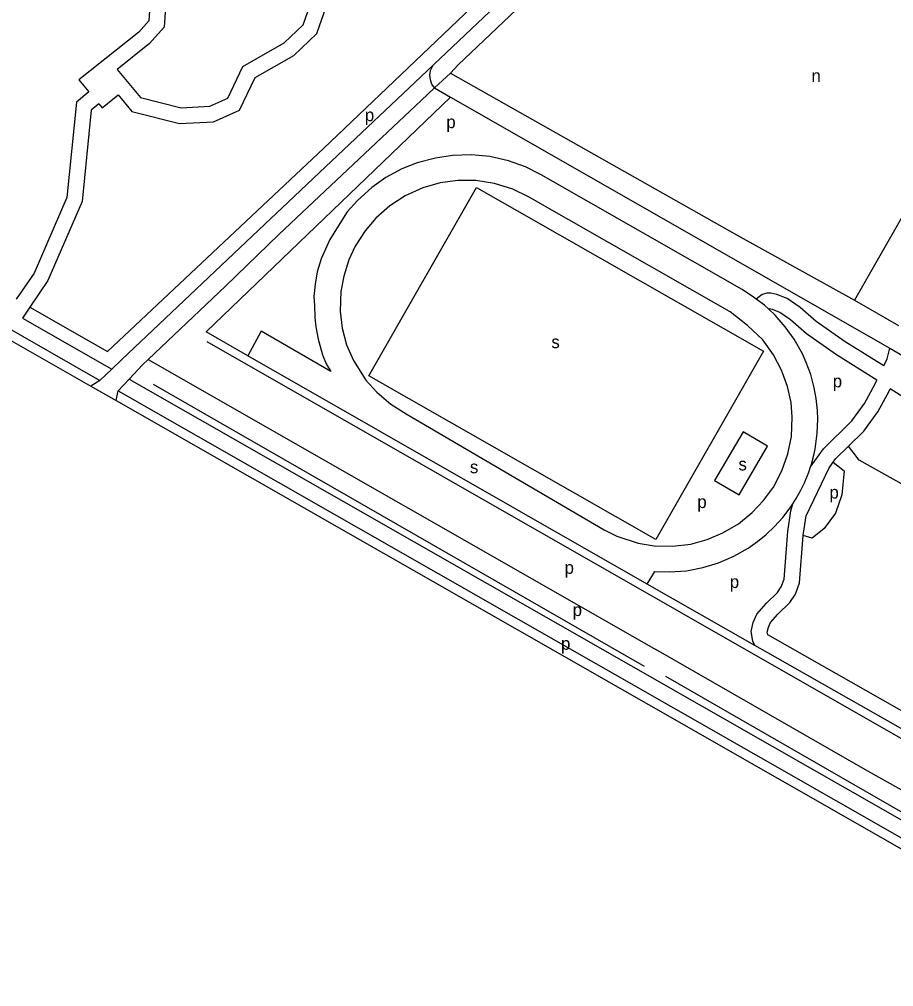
# Model space of a CAD drawing. Extents: x 157155 to 159285, y 385001 to 386651.
# Drawn here: x 157604.6 to 157882.5, y 385631.5 to 385939.1 of the extents above; entities that cross this region are included whole.
import ezdxf

# ---------------------------------------------------------------- set-up
doc = ezdxf.new("R2010")
doc.units = 0
for name, color, linetype in [('BLT_Basislijn', 7, 'Continuous'), ('BLT_Centroide', 7, 'Continuous'), ('BLT_Vlakafsluiter', 7, 'Continuous')]:
    doc.layers.add(name, color=color, linetype=linetype)

msp = doc.modelspace()

# ---------------------------------------------------------------- linework, layer by layer
at = {"layer": 'BLT_Basislijn'}
for p, q in [((157921.7, 385940.64), (157870.02, 385849.72)), ((157437.39, 385934.39), (157630.2, 385824.24)), ((157438.51, 385930.29), (157627.33, 385822.43)), ((157623.49, 385919.85), (157626.71, 385915.99)), ((157736.56, 385917.23), (157741.68, 385914.3)), ((157664, 385839.65), (157741.68, 385914.3)), ((157741.68, 385914.3), (157881.26, 385834.49)), ((157632.65, 385833.45), (157701.29, 385898)), ((157684.51, 385875.72), (157688.02, 385878.98)), ((157870.02, 385849.72), (157883.97, 385841.75)), ((157607.97, 385847.55), (157605.6, 385844.05)), ((157607.97, 385847.55), (157632.65, 385833.45)), ((157605.6, 385844.05), (157633.99, 385827.83)), ((157677.2, 385832.1), (157664, 385839.65)), ((157881.26, 385834.49), (157885.77, 385831.91)), ((157637.18, 385830.86), (157633.99, 385827.83)), ((157804.19, 385759.44), (157677.2, 385832.1)), ((157633.99, 385827.83), (157630.2, 385824.24)), ((157630.2, 385824.24), (157627.33, 385822.43)), ((157636.02, 385820.91), (157639.53, 385824.67)), ((157639.53, 385824.67), (157970.82, 385635.41)), ((157635.36, 385817.84), (157636.02, 385820.91)), ((157636.02, 385820.91), (157965.4, 385632.75)), ((157647.17, 385823.02), (157803.23, 385733.41)), ((157635.36, 385817.84), (157961.55, 385631.5)), ((157809.98, 385730.26), (157970.64, 385637.67))]:
    msp.add_line(p, q, dxfattribs=at)
for points in [[(157660.32, 386055.03), (157650.21, 386036.95), (157651.07, 386027.78), (157645.78, 386012.16), (157635.04, 385997.32), (157633.55, 385978.29), (157634.91, 385972.5), (157638.63, 385967.71), (157644.72, 385967.79), (157647.52, 385965.77), (157645.71, 385938.6), (157642.55, 385934.99), (157623.49, 385919.85)], [(157664.65, 386052.54), (157655.33, 386035.87), (157656.14, 386027.19), (157650.28, 386009.84), (157639.92, 385995.53), (157638.59, 385978.68), (157639.53, 385974.71), (157641.06, 385972.74), (157646.3, 385972.81), (157652.7, 385968.21), (157650.59, 385936.59), (157646.02, 385931.35), (157635.69, 385923.15)], [(157635.69, 385923.15), (157643.15, 385914.24), (157656.04, 385910.93), (157665.11, 385911.44), (157670.88, 385914), (157675.66, 385924.09), (157688.78, 385931.64), (157694.81, 385937.32), (157708.47, 385976.39), (157724.55, 385993.88), (157728.7, 386007.99), (157732.07, 386013.5)], [(157838.5, 386014.26), (157744.12, 385924.62), (157741.67, 385921.9)], [(157635.97, 385915.02), (157640.34, 385909.79), (157655.55, 385905.9), (157666.31, 385906.5), (157674.6, 385910.19), (157679.51, 385920.54), (157691.79, 385927.6), (157699.12, 385934.52), (157712.85, 385973.76), (157729.02, 385991.35), (157733.31, 386005.95), (157736.39, 386010.98)], [(157701.29, 385898), (157768.51, 385962.21), (157787.08, 385980.59)], [(157740.31, 385928.36), (157772, 385958.62), (157785.42, 385971.91), (157786.64, 385973.51), (157787.05, 385974.08), (157787.39, 385974.68), (157787.66, 385975.33), (157787.86, 385976), (157787.97, 385976.68), (157788.01, 385977.38), (157787.97, 385978.08), (157787.85, 385978.76), (157787.65, 385979.43), (157787.37, 385980.07), (157787.08, 385980.59)], [(157736.1, 385924.5), (157736.43, 385924.81), (157740.31, 385928.36)], [(157688.02, 385878.98), (157700, 385890.41), (157736.1, 385924.5)], [(157736.56, 385917.23), (157735.75, 385918.46), (157735.23, 385919.83), (157735.07, 385921.29), (157735.24, 385922.75), (157736.1, 385924.5)], [(157741.67, 385921.9), (157832.71, 385870.42), (157870.02, 385849.72)], [(157626.71, 385915.99), (157622.72, 385912.71), (157619.65, 385882.4), (157609.28, 385858.39), (157603.62, 385850.04)], [(157736.56, 385917.23), (157732.26, 385913.3), (157700, 385882.81), (157687.04, 385870.63), (157670.09, 385854.22), (157645.53, 385830.86)], [(157629.92, 385912.15), (157630.92, 385910.96), (157635.97, 385915.02)], [(157629.92, 385912.15), (157627.48, 385910.16), (157624.55, 385881.12), (157613.68, 385855.97), (157607.97, 385847.55)], [(157838.82, 385850.11), (157837.98, 385850.73), (157834.32, 385853.17), (157770.45, 385889.65), (157765.44, 385892.17), (157760.07, 385894.1), (157754.09, 385895.44), (157748.35, 385895.99), (157742.28, 385895.79), (157736.82, 385894.97), (157731.03, 385893.4), (157726.2, 385891.49), (157721.08, 385888.72), (157716.64, 385885.59), (157712.1, 385881.51), (157708.84, 385877.82), (157703.3, 385869.1), (157700.5, 385862.89), (157699.3, 385858.73), (157698.58, 385854.9), (157698.23, 385850.95), (157698.39, 385848.06), (157698.47, 385844.23), (157698.85, 385841.28), (157699.55, 385837.36), (157700.91, 385832.42), (157702.17, 385829.52), (157703.55, 385827.11), (157681.46, 385839.95), (157677.2, 385832.1)], [(157637.18, 385830.86), (157684.51, 385875.72)], [(157879.31, 385828.84), (157867.08, 385836.57), (157857.86, 385842.98), (157852.73, 385847.47), (157848.68, 385850.27), (157845.39, 385851.55), (157843.48, 385851.98), (157842.12, 385852), (157840.69, 385851.53), (157838.82, 385850.11)], [(157842.82, 385846.87), (157841.42, 385848.2), (157838.82, 385850.11)], [(157877.13, 385824.31), (157864.32, 385832.4), (157854.78, 385839.03), (157849.66, 385843.52), (157846.32, 385845.82), (157843.92, 385846.76), (157842.96, 385846.97), (157842.82, 385846.87)], [(157856.04, 385796.73), (157856.32, 385797.58), (157857.08, 385800.44), (157857.5, 385802.43), (157858.2, 385807.52), (157858.37, 385811.88), (157858.27, 385814.72), (157857.86, 385818.52), (157857.24, 385821.94), (157856.12, 385826.11), (157854.72, 385829.93), (157853.47, 385832.69), (157850.82, 385837.37), (157847.99, 385841.34), (157844.81, 385844.98), (157842.82, 385846.87)], [(157664.14, 385836.65), (157964.44, 385664.94), (157960.27, 385656.22), (157975.98, 385646.81)], [(157879.31, 385828.84), (157880.4, 385831.11), (157881.26, 385834.49)], [(157639.53, 385824.67), (157643.74, 385829.17), (157645.53, 385830.86)], [(157645.53, 385830.86), (157806.93, 385738.71)], [(157856.04, 385796.73), (157860.13, 385802.54), (157869.15, 385811.36), (157873.21, 385816.93), (157876.56, 385823.13), (157877.13, 385824.31)], [(157868.14, 385803.38), (157872.95, 385808.08), (157877.45, 385814.26), (157881.01, 385820.85), (157881.38, 385821.62)], [(157936.64, 385795.09), (157918.91, 385800.1), (157905.22, 385808.69), (157889.77, 385816.32), (157881.38, 385821.62)], [(157863.21, 385798.23), (157863.95, 385799.29), (157868.14, 385803.38)], [(157980.12, 385742.87), (157965.34, 385753.22), (157952.85, 385759.3), (157931.21, 385769.57), (157923.59, 385769.74), (157871.53, 385798.9), (157868.14, 385803.38)], [(157850.45, 385785.05), (157851.54, 385786.72), (157853.02, 385789.38), (157854.15, 385791.74), (157855.51, 385795.1), (157856.04, 385796.73)], [(157863.21, 385798.23), (157866.8, 385795.53), (157866.04, 385787.9), (157864.02, 385782.09), (157860.37, 385777.13), (157856.62, 385774.05), (157853.73, 385774.94)], [(157854.63, 385781.18), (157861.99, 385796.49)], [(157861.99, 385796.49), (157863.21, 385798.23)], [(157804.19, 385759.44), (157806.58, 385763.46), (157811.25, 385763.34), (157816.64, 385763.75), (157821.79, 385764.78), (157826.83, 385766.28), (157831.64, 385768.4), (157836.25, 385770.92), (157839.18, 385773.01), (157841.99, 385775.3), (157844.64, 385777.77), (157847.24, 385780.66), (157849.57, 385783.69), (157850.45, 385785.05)], [(157838.31, 385740), (157837.69, 385741.33), (157837.24, 385744.4), (157837.87, 385747.31), (157839.04, 385749.98), (157842.05, 385753.41), (157845.59, 385756.86), (157846.76, 385758.63), (157847.67, 385761.03), (157848.81, 385776.22), (157849.82, 385782.81), (157850.45, 385785.05)], [(157853.73, 385774.94), (157853.78, 385775.66), (157854.63, 385781.18)], [(157842.44, 385743.41), (157842.32, 385744.23), (157842.65, 385745.76), (157843.31, 385747.26), (157845.68, 385749.96), (157849.47, 385753.66), (157851.23, 385756.33), (157852.6, 385759.93), (157853.73, 385774.94)], [(157838.31, 385740), (157804.19, 385759.44)], [(157951.23, 385681.58), (157844.91, 385742), (157842.44, 385743.41)], [(157953.87, 385655.46), (157874.22, 385700), (157806.93, 385738.71)], [(157949.38, 385676.88), (157842.44, 385737.65), (157838.31, 385740)]]:
    msp.add_lwpolyline(points, dxfattribs=at)
for points in [[(157766.42, 385882.6), (157761.45, 385885.02), (157755.6, 385886.87), (157749.73, 385887.77), (157744, 385887.8), (157738.39, 385887.07), (157732.81, 385885.49), (157727.23, 385882.94), (157722.33, 385879.73), (157717.93, 385875.82), (157714.48, 385871.78), (157711.38, 385866.94), (157709.35, 385862.63), (157707.69, 385857.44), (157706.81, 385852.49), (157706.58, 385846.31), (157707.19, 385840.82), (157708.62, 385835.6), (157710.77, 385830.57), (157714.75, 385824.34), (157718.19, 385820.47), (157722.66, 385816.67), (157727.55, 385813.63), (157790.45, 385776.74), (157794.54, 385774.69), (157801.24, 385772.5), (157806.41, 385771.65), (157812.22, 385771.51), (157818, 385772.22), (157823.25, 385773.64), (157828.23, 385775.74), (157833.17, 385778.69), (157837.55, 385782.21), (157841.16, 385786.04), (157844.26, 385790.36), (157846.92, 385795.46), (157848.86, 385800.91), (157849.97, 385806.4), (157850.27, 385812.58), (157849.87, 385817.19), (157848.78, 385822.27), (157846.87, 385827.56), (157844.31, 385832.43), (157840.9, 385837.14), (157836.07, 385841.74), (157830.47, 385846.01)], [(157715.71, 385825.75), (157749.91, 385885.63), (157841.08, 385833.6), (157806.85, 385773.71)], [(157825.58, 385792.41), (157833.37, 385787.86), (157842.42, 385803.39), (157834.63, 385807.93)]]:
    msp.add_lwpolyline(points, close=True, dxfattribs=at)
at = {"layer": 'BLT_Vlakafsluiter'}
msp.add_line((157627.33, 385822.43), (157635.36, 385817.84), dxfattribs=at)
msp.add_lwpolyline([(157741.67, 385921.9), (157736.56, 385917.23)], dxfattribs=at)

# ---------------------------------------------------------------- texts
at = {"layer": 'BLT_Centroide'}
for s, p in [('n', (157856.36, 385919.13)), ('p', (157714.42, 385906.67)), ('p', (157740.3, 385904.45)), ('s', (157773.69, 385834.5)), ('p', (157863.12, 385822.05)), ('s', (157747.8, 385794.74)), ('s', (157833.16, 385795.63)), ('p', (157820.08, 385783.68)), ('p', (157862.07, 385786.69)), ('p', (157777.89, 385762.76)), ('p', (157830.4, 385758.25)), ('p', (157780.47, 385749.34)), ('p', (157776.76, 385738.61))]:
    msp.add_text(s, height=4, dxfattribs=at).set_placement(p)

doc.saveas('drawing.dxf')
